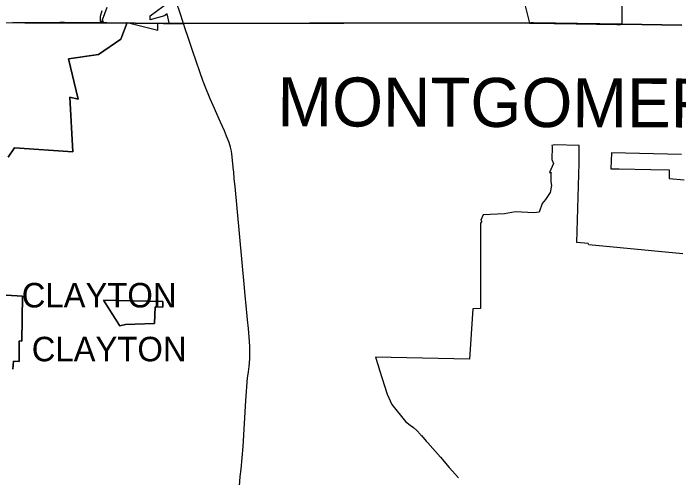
# Model space of a CAD drawing. Extents: x 0 to 34, y 0 to 22.
# Drawn here: x 4.7244 to 4.9426, y 15.9771 to 16.1294 of the extents above; entities that cross this region are included whole.
import ezdxf

# ---------------------------------------------------------------- set-up
doc = ezdxf.new("R2010")
doc.units = 0
for name, color, linetype in [('GM_X_Corporation', 7, 'Continuous'), ('GM_X_Corporation_Text', 7, 'Continuous'), ('GM_X_County', 7, 'Continuous'), ('GM_X_County_Text', 7, 'Continuous'), ('GM_X_State_Route', 7, 'Continuous')]:
    doc.layers.add(name, color=color, linetype=linetype)

msp = doc.modelspace()

# ---------------------------------------------------------------- linework, layer by layer
at = {"layer": 'GM_X_Corporation'}
for points in [[(4.89036, 16.13944), (4.89367, 16.12612), (4.89406, 16.12612), (4.89449, 16.12611), (4.90891, 16.12594), (4.92225, 16.12577), (4.92225, 16.12577), (4.92352, 16.12576), (4.92401, 16.12579), (4.92401, 16.13828)], [(4.72264, 16.08225), (4.72482, 16.08525), (4.74384, 16.08397), (4.74289, 16.10187), (4.74561, 16.10124), (4.74247, 16.11443), (4.75235, 16.11593), (4.75963, 16.12092), (4.76169, 16.12634), (4.77178, 16.12385), (4.77178, 16.12615), (4.7755, 16.12623), (4.7748, 16.12924), (4.7739, 16.12854), (4.76929, 16.12721), (4.76929, 16.12861), (4.77543, 16.13314)], [(4.75499, 16.13133), (4.75353, 16.12714), (4.75394, 16.12666), (4.75297, 16.12673), (4.75297, 16.12847), (4.75353, 16.13028)], [(4.70734, 16.12633), (4.72913, 16.12627), (4.72937, 16.12627), (4.756, 16.12631), (4.7576, 16.1263), (4.76169, 16.12634), (4.75963, 16.12092), (4.75235, 16.11593), (4.74247, 16.11443), (4.74561, 16.10124), (4.74289, 16.10187), (4.74384, 16.08397), (4.72482, 16.08525), (4.72264, 16.08225)], [(4.94392, 16.05051), (4.91309, 16.05342), (4.91291, 16.05387), (4.90913, 16.05426), (4.90988, 16.08027), (4.90991, 16.08602), (4.90175, 16.08623), (4.90094, 16.08599), (4.90109, 16.08563), (4.90101, 16.08147), (4.90148, 16.08015), (4.90022, 16.07724), (4.90086, 16.0772), (4.90061, 16.07694), (4.90058, 16.07409), (4.90082, 16.07292), (4.90043, 16.07064), (4.8989, 16.0683), (4.89774, 16.06698), (4.89675, 16.06422), (4.89511, 16.06393), (4.88901, 16.06431), (4.88541, 16.06359), (4.87845, 16.06332), (4.87773, 16.06152), (4.87803, 16.06119), (4.87758, 16.06053), (4.87754, 16.03259), (4.87501, 16.03244), (4.87397, 16.01597), (4.84313, 16.01666), (4.84398, 16.01385), (4.8444, 16.01235), (4.84691, 16.00452), (4.84854, 16.00111), (4.85301, 15.99555), (4.85452, 15.99435), (4.85557, 15.99351), (4.85673, 15.99258), (4.85784, 15.99131), (4.85805, 15.99107), (4.85815, 15.99095), (4.85821, 15.99089), (4.85978, 15.9891), (4.8603, 15.9885), (4.86443, 15.98379), (4.86733, 15.98048), (4.87038, 15.97701)], [(4.94349, 16.08314), (4.92053, 16.08368), (4.92032, 16.07844), (4.92303, 16.07838), (4.93339, 16.07818), (4.93947, 16.07806), (4.93939, 16.07527), (4.94437, 16.07477)], [(4.72419, 16.01268), (4.72443, 16.01528), (4.7263, 16.01521), (4.72634, 16.02193), (4.7272, 16.0219), (4.72734, 16.03661), (4.71655, 16.03724)], [(4.71655, 16.03724), (4.72734, 16.03661), (4.7272, 16.0219), (4.72634, 16.02193), (4.7263, 16.01521), (4.72443, 16.01528), (4.72419, 16.01268)]]:
    msp.add_lwpolyline(points, dxfattribs=at)
for points in [[(4.77065, 16.02767), (4.77084, 16.03308), (4.77338, 16.03301), (4.77339, 16.03484), (4.75394, 16.03529), (4.75925, 16.02706), (4.75933, 16.02692), (4.76114, 16.02729), (4.76417, 16.02741)], [(4.75394, 16.03529), (4.77339, 16.03484), (4.77338, 16.03301), (4.77084, 16.03308), (4.77065, 16.02767), (4.76417, 16.02741), (4.76114, 16.02729), (4.75933, 16.02692)]]:
    msp.add_lwpolyline(points, close=True, dxfattribs=at)
at = {"layer": 'GM_X_County'}
for points in [[(4.7242, 16.12633), (4.72815, 16.12629), (4.72941, 16.12628), (4.73189, 16.12628), (4.73511, 16.1263), (4.7396, 16.12634), (4.74113, 16.12635), (4.748, 16.12628), (4.74934, 16.12628), (4.75152, 16.12628), (4.75352, 16.12629), (4.75507, 16.12629), (4.77361, 16.12608), (4.78016, 16.12608), (4.82152, 16.12611), (4.82541, 16.12611), (4.83274, 16.12611), (4.89403, 16.12625), (4.89491, 16.12623), (4.92395, 16.12579), (4.94355, 16.12552)], [(4.94355, 16.12552), (4.92395, 16.12579), (4.89491, 16.12623), (4.89403, 16.12625), (4.83274, 16.12611), (4.82541, 16.12611), (4.82152, 16.12611), (4.78016, 16.12608), (4.77361, 16.12608), (4.75507, 16.12629), (4.75352, 16.12629), (4.75152, 16.12628), (4.74934, 16.12628), (4.748, 16.12628), (4.74113, 16.12635), (4.7396, 16.12634), (4.73511, 16.1263), (4.73189, 16.12628), (4.72941, 16.12628), (4.72815, 16.12629), (4.7242, 16.12633)]]:
    msp.add_lwpolyline(points, dxfattribs=at)
at = {"layer": 'GM_X_State_Route'}
msp.add_line((4.80052, 16.03561), (4.80006, 16.0406), dxfattribs=at)
for points in [[(4.78018, 16.12603), (4.77893, 16.12977), (4.77795, 16.13266), (4.77714, 16.13513)], [(4.78666, 16.10704), (4.78328, 16.11691), (4.78157, 16.12183), (4.7807, 16.12433), (4.78018, 16.12603)], [(4.79659, 16.078), (4.79606, 16.08329), (4.79591, 16.08423), (4.7956, 16.08554), (4.79519, 16.08704), (4.79433, 16.08913), (4.7936, 16.09088), (4.79235, 16.09374), (4.78996, 16.09913), (4.78896, 16.1014), (4.78725, 16.10536), (4.78674, 16.10681), (4.78666, 16.10704)], [(4.80006, 16.0406), (4.79708, 16.07265), (4.79684, 16.07515), (4.79665, 16.07741), (4.79659, 16.078)], [(4.79837, 15.97141), (4.79862, 15.97583), (4.79879, 15.97751), (4.79909, 15.97985), (4.79973, 15.98737), (4.80063, 16.00242), (4.80119, 16.00986), (4.80153, 16.01167), (4.80164, 16.01276), (4.80172, 16.01343), (4.80191, 16.0162), (4.80195, 16.02015), (4.80187, 16.02175), (4.80146, 16.02598), (4.80114, 16.02891), (4.8006, 16.03477), (4.80052, 16.03561)]]:
    msp.add_lwpolyline(points, dxfattribs=at)

# ---------------------------------------------------------------- texts
at = {"layer": 'GM_X_Corporation_Text'}
for p in [(4.72713, 16.03293), (4.73042, 16.01526)]:
    msp.add_text('CLAYTON', height=0.008037, rotation=0, dxfattribs=at).set_placement(p)
at = {"layer": 'GM_X_County_Text'}
msp.add_text('MONTGOMERY COUNTY', height=0.016074, rotation=359.824, dxfattribs=at).set_placement((4.81096, 16.09235))

doc.saveas('drawing.dxf')
